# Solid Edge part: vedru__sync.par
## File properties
Author: KULL
Template: Iso Metric Part.par
Last saved by: KULL
Revision: 3
Application: Solid Edge
Accuracy: 0,990
Face Style: Model Default
Fill Style: Normal
Coef. of Thermal Exp: 0.0
Thermal Conductivity: 0.0
Specific Heat: 0.0
Modulus of Elasticity: 0.0
Poisson's Ratio: 0.0
Yield Stress: 0.0
Ultimate Stress: 0.0
Elongation: 0.0
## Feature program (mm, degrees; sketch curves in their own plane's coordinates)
base feature "unnamed BaseFeature 1"
Other named dimensions: "HelixProtrusion_1": NumberOfTurns = 4.5; Accuracy = 1
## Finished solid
Body 1: sheet body, 12 faces, 14 edges, 4 vertices.
  Faces by surface: plane 12
  Edges by curve: intersection 8, circle 6
Body 2: solid body, 3 faces, 4 edges, 4 vertices.
  Faces by surface: torus 2, spline 1
  Edges by curve: circle 2, intersection 2
Bounding box of the edges (mm; curved faces can reach further): 6.787 x 25.936 x 32.228, from (-6.7872, 53.5904, 11.5548) to (0, 79.5263, 43.7826).
Toroidal faces (ring radius, tube radius in mm): R5.8516 r1.2 x2
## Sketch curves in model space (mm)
line (0, 73.196, 15.5693) -> (0, 59.9207, 39.7682)
circle centre (0, 54.7904, 36.9537) radius 1.2
circle centre (0, 78.3263, 18.3837) radius 1.2
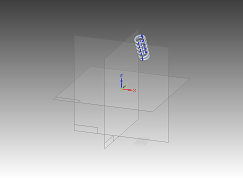
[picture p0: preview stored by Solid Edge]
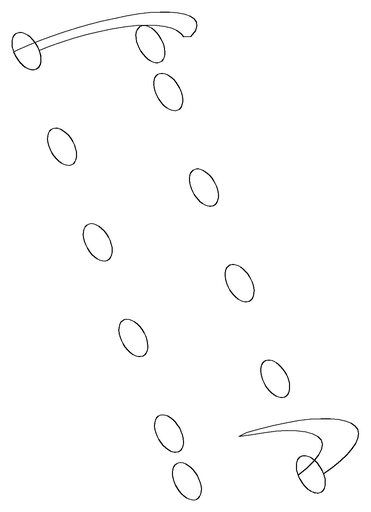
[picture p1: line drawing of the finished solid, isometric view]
